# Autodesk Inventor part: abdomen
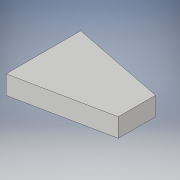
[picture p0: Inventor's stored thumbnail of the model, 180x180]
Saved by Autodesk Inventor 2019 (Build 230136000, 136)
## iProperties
Created: 2020-07
Part Number: abdomen
Material: 一般
Document SubType Name: Modeling
Designer: kikut
Density: 1 g/cm^3
Appearance: 既定
Author: kikut
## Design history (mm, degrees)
sketch "スケッチ1"
  geometry: L1 (0, -0.02)-(0, 0.02); L2 (0.02, 0)-(-0.12, 0) reference; L3 (0, 0.02)-(-0.05, 0.009); L4 (-0.05, 0.009)-(-0.1, 0.023); L5 (-0.1, 0.023)-(-0.1, -0.021); L6 (-0.1, -0.021)-(-0.05, -0.011); L7 (-0.05, -0.011)-(0, -0.02); 1 further point
  constraints: 12 end point, 1 parallel, 1 point on line
  dimensions: "d0" = 0.04 distance of L1.start L1.end; "d1" = 90 deg angle of L1 L2; "d2" = 0.1 distance between parallel lines of L5 L1; "d3" = 0.05 distance from line of L3.end L1; "d4" = 0.05 distance from line of L6.end L1; "d5" = 0.02 distance of L3.end L6.end
extrude "押し出し1" new body sketch "スケッチ1" stored distance "d6" = 0.01; taper "d7" = 0 deg
sketch "スケッチ2"
  geometry: L1 (0.11, 0.03)-(0.05, 0.03); L2 (0.05, 0.03)-(0.05, -0.03); L3 (0.05, -0.03)-(0.11, -0.03); L4 (0.11, -0.03)-(0.11, 0.03); L5 (0, 0.02)-(0, -0.02) reference; 1 further point
  constraints: 8 end point, 2 parallel, 1 horizontal, 1 perpendicular
  dimensions: "d8" = 0.06 distance of L1.start L1.end; "d9" = 0.05 distance between parallel lines of L2 L5; "d10" = 0.06 distance of L3.end L1.start; "d11" = 0.03 distance from line of L1 point (0, 0)
extrude "押し出し2" cut sketch "スケッチ2" distance "d12" = 10; taper "d13" = 0 deg
node "ソリッド1"
